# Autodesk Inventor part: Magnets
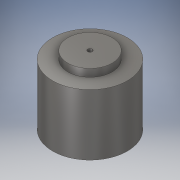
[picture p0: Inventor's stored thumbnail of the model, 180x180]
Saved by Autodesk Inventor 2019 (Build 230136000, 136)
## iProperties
Created: 2019-05
Part Number: Magnets
Material: Iron, Malleable
Document SubType Name: Modeling
Designer: Administrator
Density: 7.15 g/cm^3
Appearance: Semi-Polished
Author: Administrator
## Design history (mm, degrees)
sketch "Sketch1"
  geometry: C1 r 24.5 at (0, 0); 1 further point
  constraints: 1 centre point, 1 coincident
  dimensions: "d0" = 49 diameter of C1
extrude "Extrusion1" new body sketch "Sketch1" distance "d1" = 40; taper "d2" = 0 deg
sketch "Sketch2"
  geometry: C1 r 14.5 at (0, 0); 1 further point
  constraints: 1 centre point, 1 coincident
  dimensions: "d3" = 29 diameter of C1
extrude "Extrusion2" join sketch "Sketch2" distance "d4" = 5; taper "d5" = 0 deg
sketch "Sketch3"
  geometry: C1 r 1.5 at (0, 0); 1 further point
  constraints: 1 centre point, 1 coincident
  dimensions: "d6" = 3 diameter of C1
extrude "Extrusion3" cut sketch "Sketch3" distance "d7" = 45; taper "d8" = 0 deg
body "Solid1"
